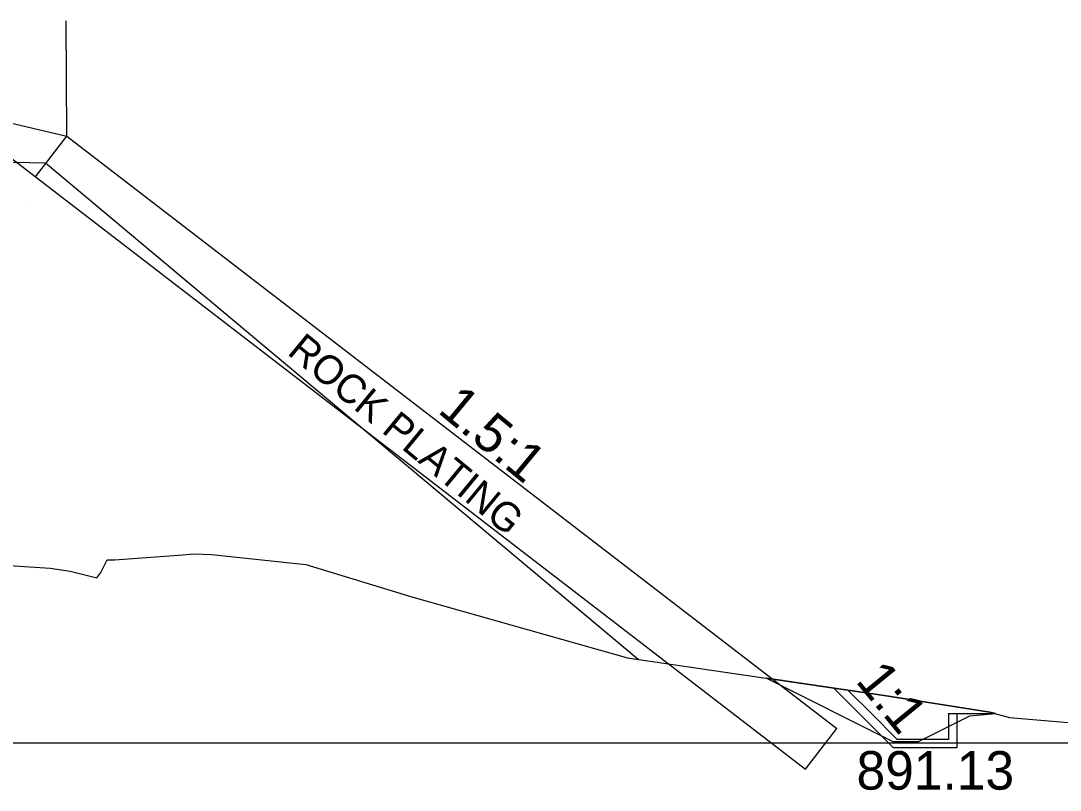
# Model space of a CAD drawing. Extents: x -26 to 1640245, y -10 to 842531.
# Drawn here: x 179.04 to 219.5, y 998.15 to 1028.09 of the extents above; entities that cross this region are included whole.
import ezdxf

# ---------------------------------------------------------------- set-up
doc = ezdxf.new("R2010")
doc.units = 0
for name, color, linetype in [('Exist Cross Section Cell', 7, 'Continuous'), ('Exist XS Ground Line', 7, 'Continuous'), ('Prop CMT Concrete Ditch', 7, 'Continuous'), ('Prop CMT Slope Grass', 7, 'Continuous'), ('Prop XS Class B Stone Ditch Liner', 7, 'Continuous'), ('Prop XS Ditch Standard Text', 7, 'Continuous'), ('Prop XS Side Slope Text', 7, 'Continuous'), ('Scratch_Level_2', 7, 'Continuous'), ('Scratch_Level_3', 7, 'Continuous'), ('Scratch_Level_5', 7, 'Continuous')]:
    doc.layers.add(name, color=color, linetype=linetype)

msp = doc.modelspace()

# ---------------------------------------------------------------- linework, layer by layer
at = {"layer": 'Exist Cross Section Cell'}
msp.add_line((150, 1000), (300, 1000), dxfattribs=at)
at = {"layer": 'Exist XS Ground Line'}
for p, q in [((182.156, 1006.627), (182.408, 1007.115)), ((182.408, 1007.115), (182.685, 1007.122)), ((182.685, 1007.122), (185.349, 1007.317)), ((185.349, 1007.317), (185.794, 1007.353)), ((185.794, 1007.353), (186.465, 1007.322)), ((186.465, 1007.322), (190.131, 1006.929)), ((178.395, 1006.913), (179.787, 1006.824)), ((179.787, 1006.824), (180.181, 1006.788)), ((180.181, 1006.788), (180.963, 1006.68)), ((180.963, 1006.68), (181.997, 1006.412)), ((181.997, 1006.412), (182.156, 1006.627)), ((190.131, 1006.929), (194.265, 1005.683)), ((194.265, 1005.683), (202.65, 1003.297)), ((202.65, 1003.297), (212.644, 1001.838)), ((212.644, 1001.838), (216.759, 1001.193)), ((216.759, 1001.193), (217.525, 1000.984)), ((217.525, 1000.984), (221.379, 1000.647))]:
    msp.add_line(p, q, dxfattribs=at)
at = {"layer": 'Prop CMT Concrete Ditch'}
for p, q in [((213.009, 999.799), (210.684, 1002.124)), ((210.684, 1002.124), (211.236, 1002.044)), ((215.147, 1001.132), (215.147, 1000.132)), ((215.147, 1001.132), (215.48, 1001.132)), ((215.48, 1001.132), (216.98, 1001.132)), ((215.48, 1001.132), (216.98, 1001.132)), ((215.48, 1001.132), (215.48, 999.799)), ((215.147, 1000.132), (213.147, 1000.132)), ((215.48, 999.799), (213.009, 999.799))]:
    msp.add_line(p, q, dxfattribs=at)
msp.add_lwpolyline([(213.147, 1000.132), (212.147, 1001.132), (211.243, 1002.037)], dxfattribs=at)
at = {"layer": 'Prop CMT Slope Grass'}
msp.add_line((177.157, 1023.913), (209.582, 998.971), dxfattribs=at)
at = {"layer": 'Prop XS Class B Stone Ditch Liner'}
for p, q in [((177.904, 1024.286), (180.832, 1023.609)), ((179.613, 1022.024), (180.832, 1023.609)), ((180.832, 1023.609), (210.801, 1000.556)), ((209.582, 998.971), (210.801, 1000.556))]:
    msp.add_line(p, q, dxfattribs=at)
at = {"layer": 'Scratch_Level_2'}
for p, q in [((208.066, 1002.506), (212.98, 1000.049)), ((213.98, 1000.049), (215.98, 1001.049)), ((215.98, 1001.049), (216.98, 1001.132)), ((216.98, 1001.132), (216.759, 1001.193)), ((212.98, 1000.049), (213.98, 1000.049))]:
    msp.add_line(p, q, dxfattribs=at)
msp.add_lwpolyline([(216.759, 1001.193), (212.644, 1001.838), (208.066, 1002.506)], dxfattribs=at)
at = {"layer": 'Scratch_Level_3'}
for p, q in [((179.999, 1022.548), (175.436, 1022.638)), ((203.066, 1003.236), (179.999, 1022.548))]:
    msp.add_line(p, q, dxfattribs=at)
msp.add_lwpolyline([(178.395, 1006.913), (179.787, 1006.824), (180.181, 1006.788), (180.963, 1006.68), (181.997, 1006.412), (182.156, 1006.627), (182.408, 1007.115), (182.685, 1007.122), (185.349, 1007.317), (185.794, 1007.353), (186.465, 1007.322), (190.131, 1006.929), (194.265, 1005.683), (202.65, 1003.297), (203.066, 1003.236)], dxfattribs=at)
at = {"layer": 'Scratch_Level_5'}
for p, q in [((180.832, 1023.616), (180.812, 1028.092)), ((179.176, 1020.835), (179.176, 1020.835))]:
    msp.add_line(p, q, dxfattribs=at)

# ---------------------------------------------------------------- texts
at = {"layer": 'Prop XS Ditch Standard Text'}
msp.add_text('891.13', height=1.5, dxfattribs=at).set_placement((211.57, 998.174))
at = {"layer": 'Prop XS Side Slope Text'}
for s, height, rotation, p in [('ROCK PLATING', 1.125, 320.4211, (189.372, 1015.144)), ('1.5:1', 1.5, 320.4211, (195.226, 1012.874)), ('1:1', 1.5, 309.2203, (211.5, 1002.396))]:
    msp.add_text(s, height=height, rotation=rotation, dxfattribs=at).set_placement(p)

doc.saveas('drawing.dxf')
